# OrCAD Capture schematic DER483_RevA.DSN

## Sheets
1 PAGE2: size C
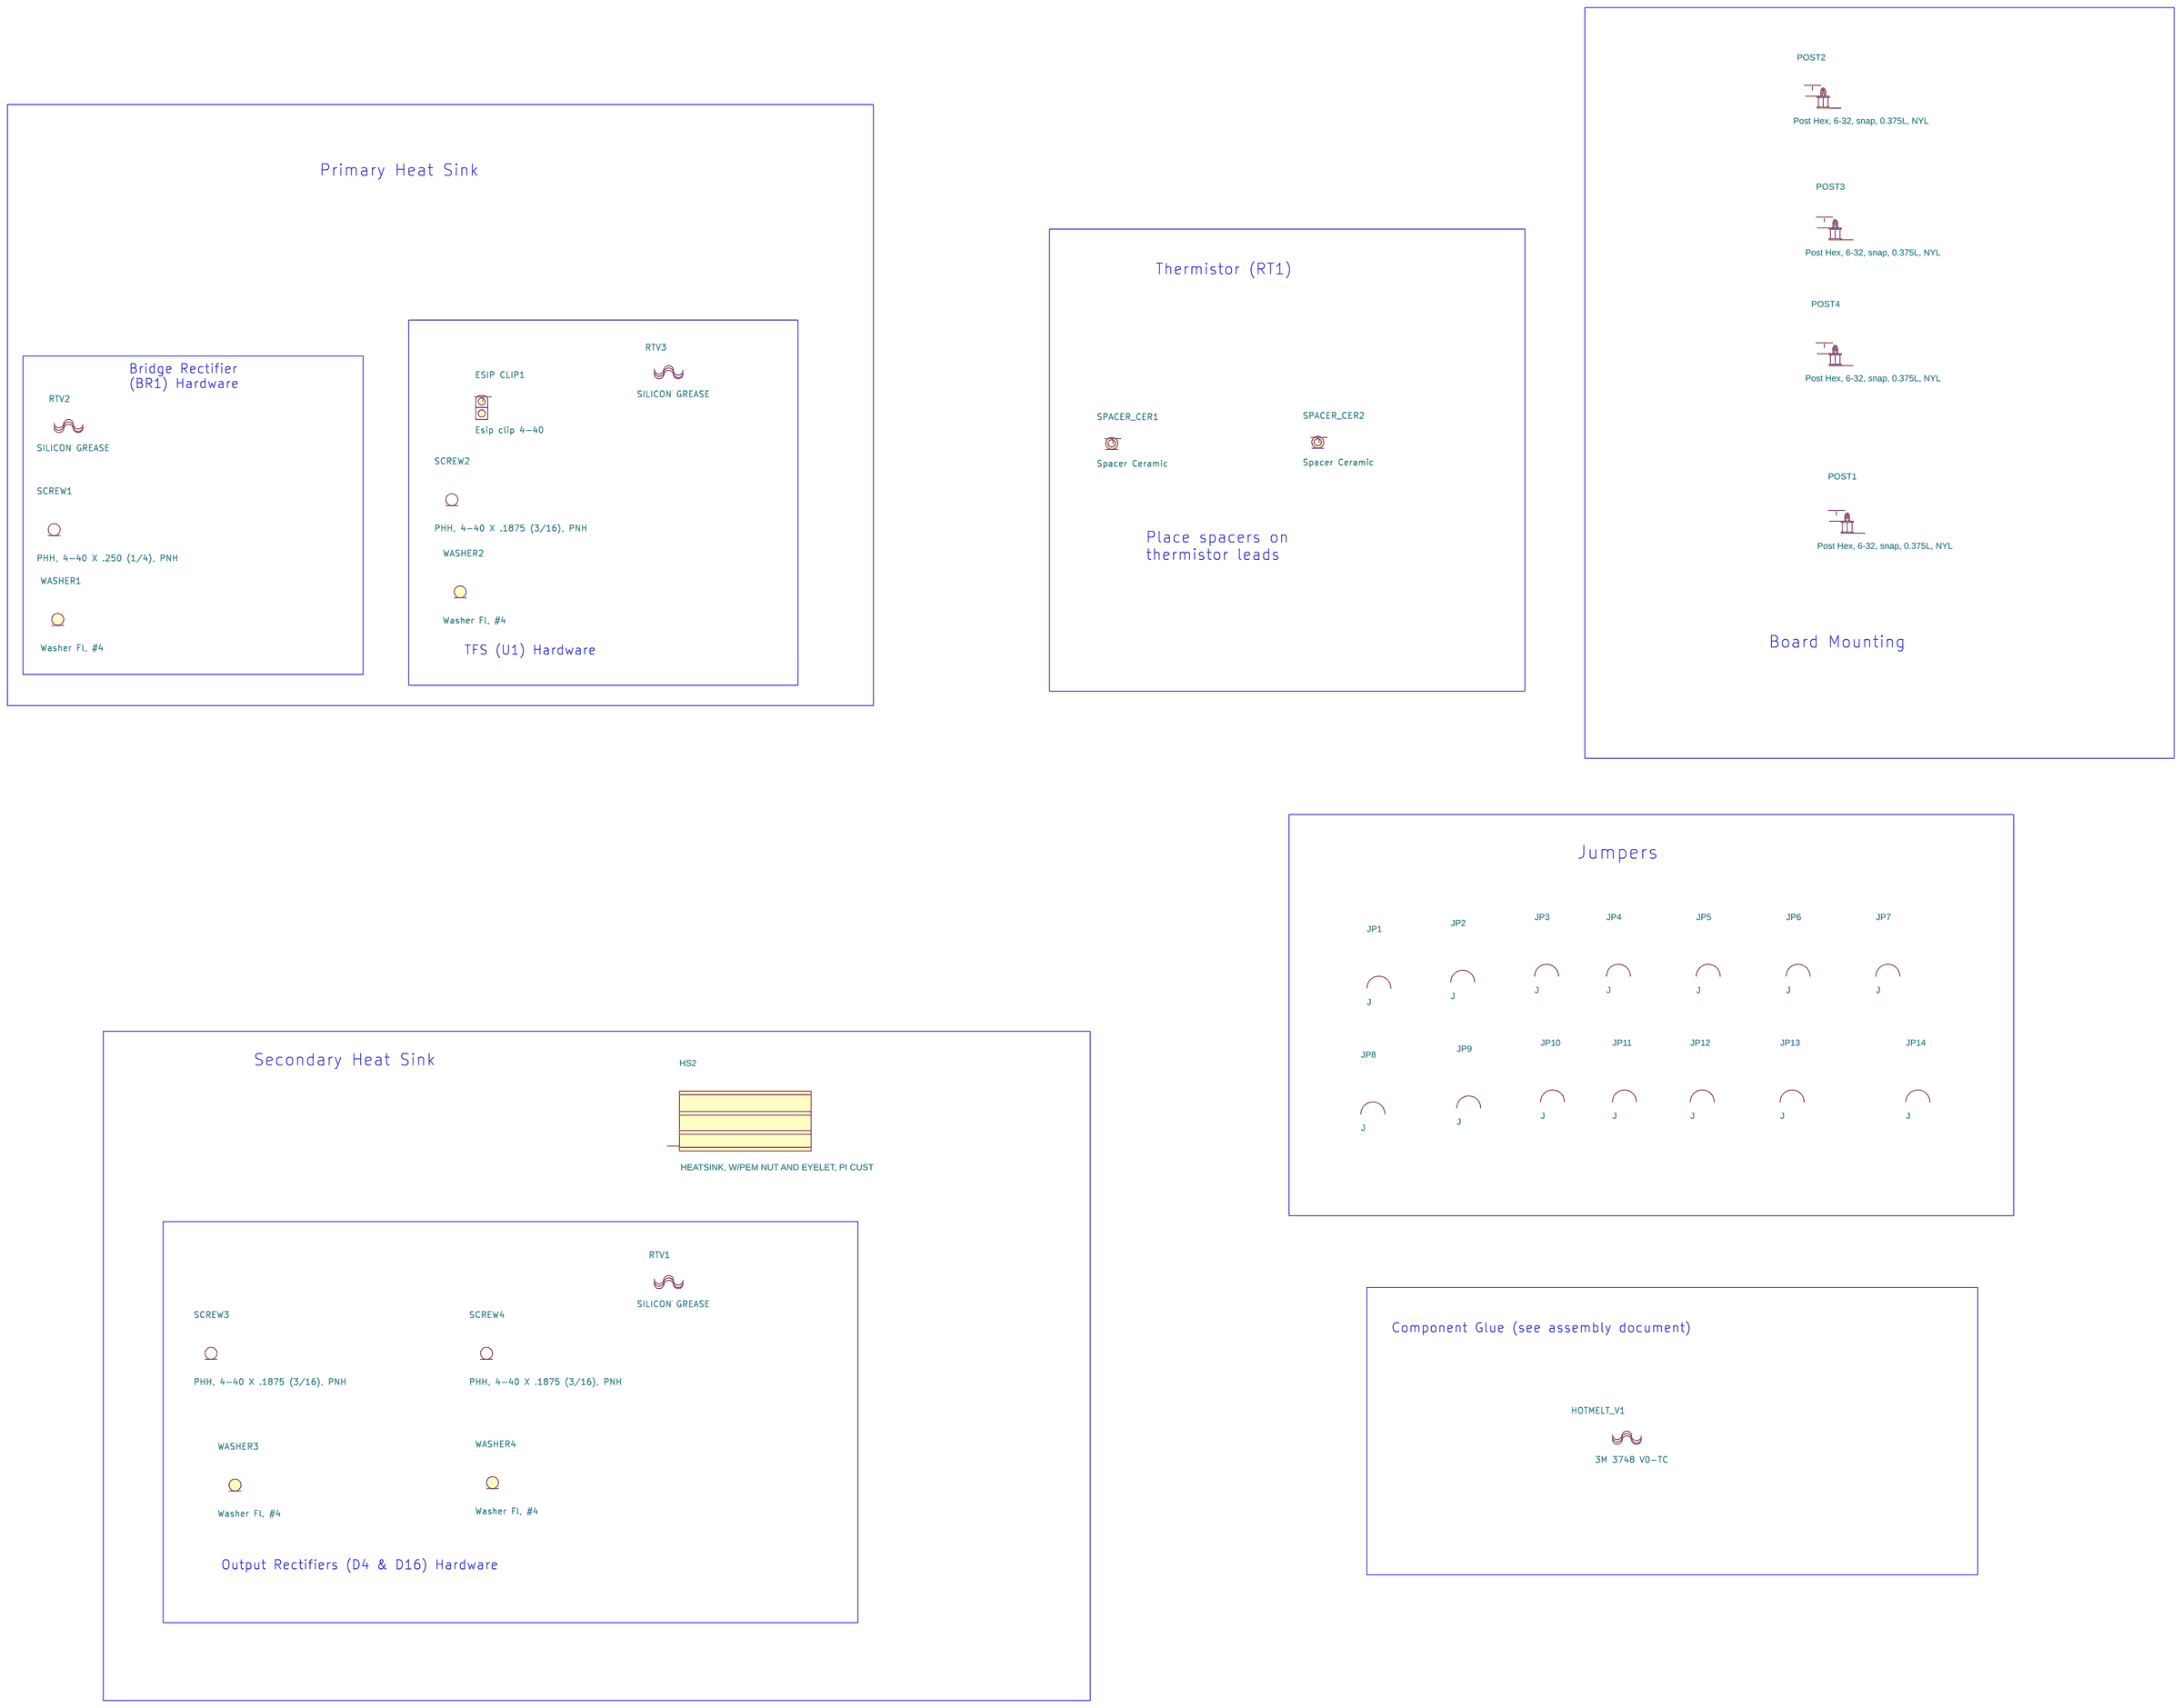
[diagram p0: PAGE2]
2 PAGE1: size C; title: DER-309; rev: A
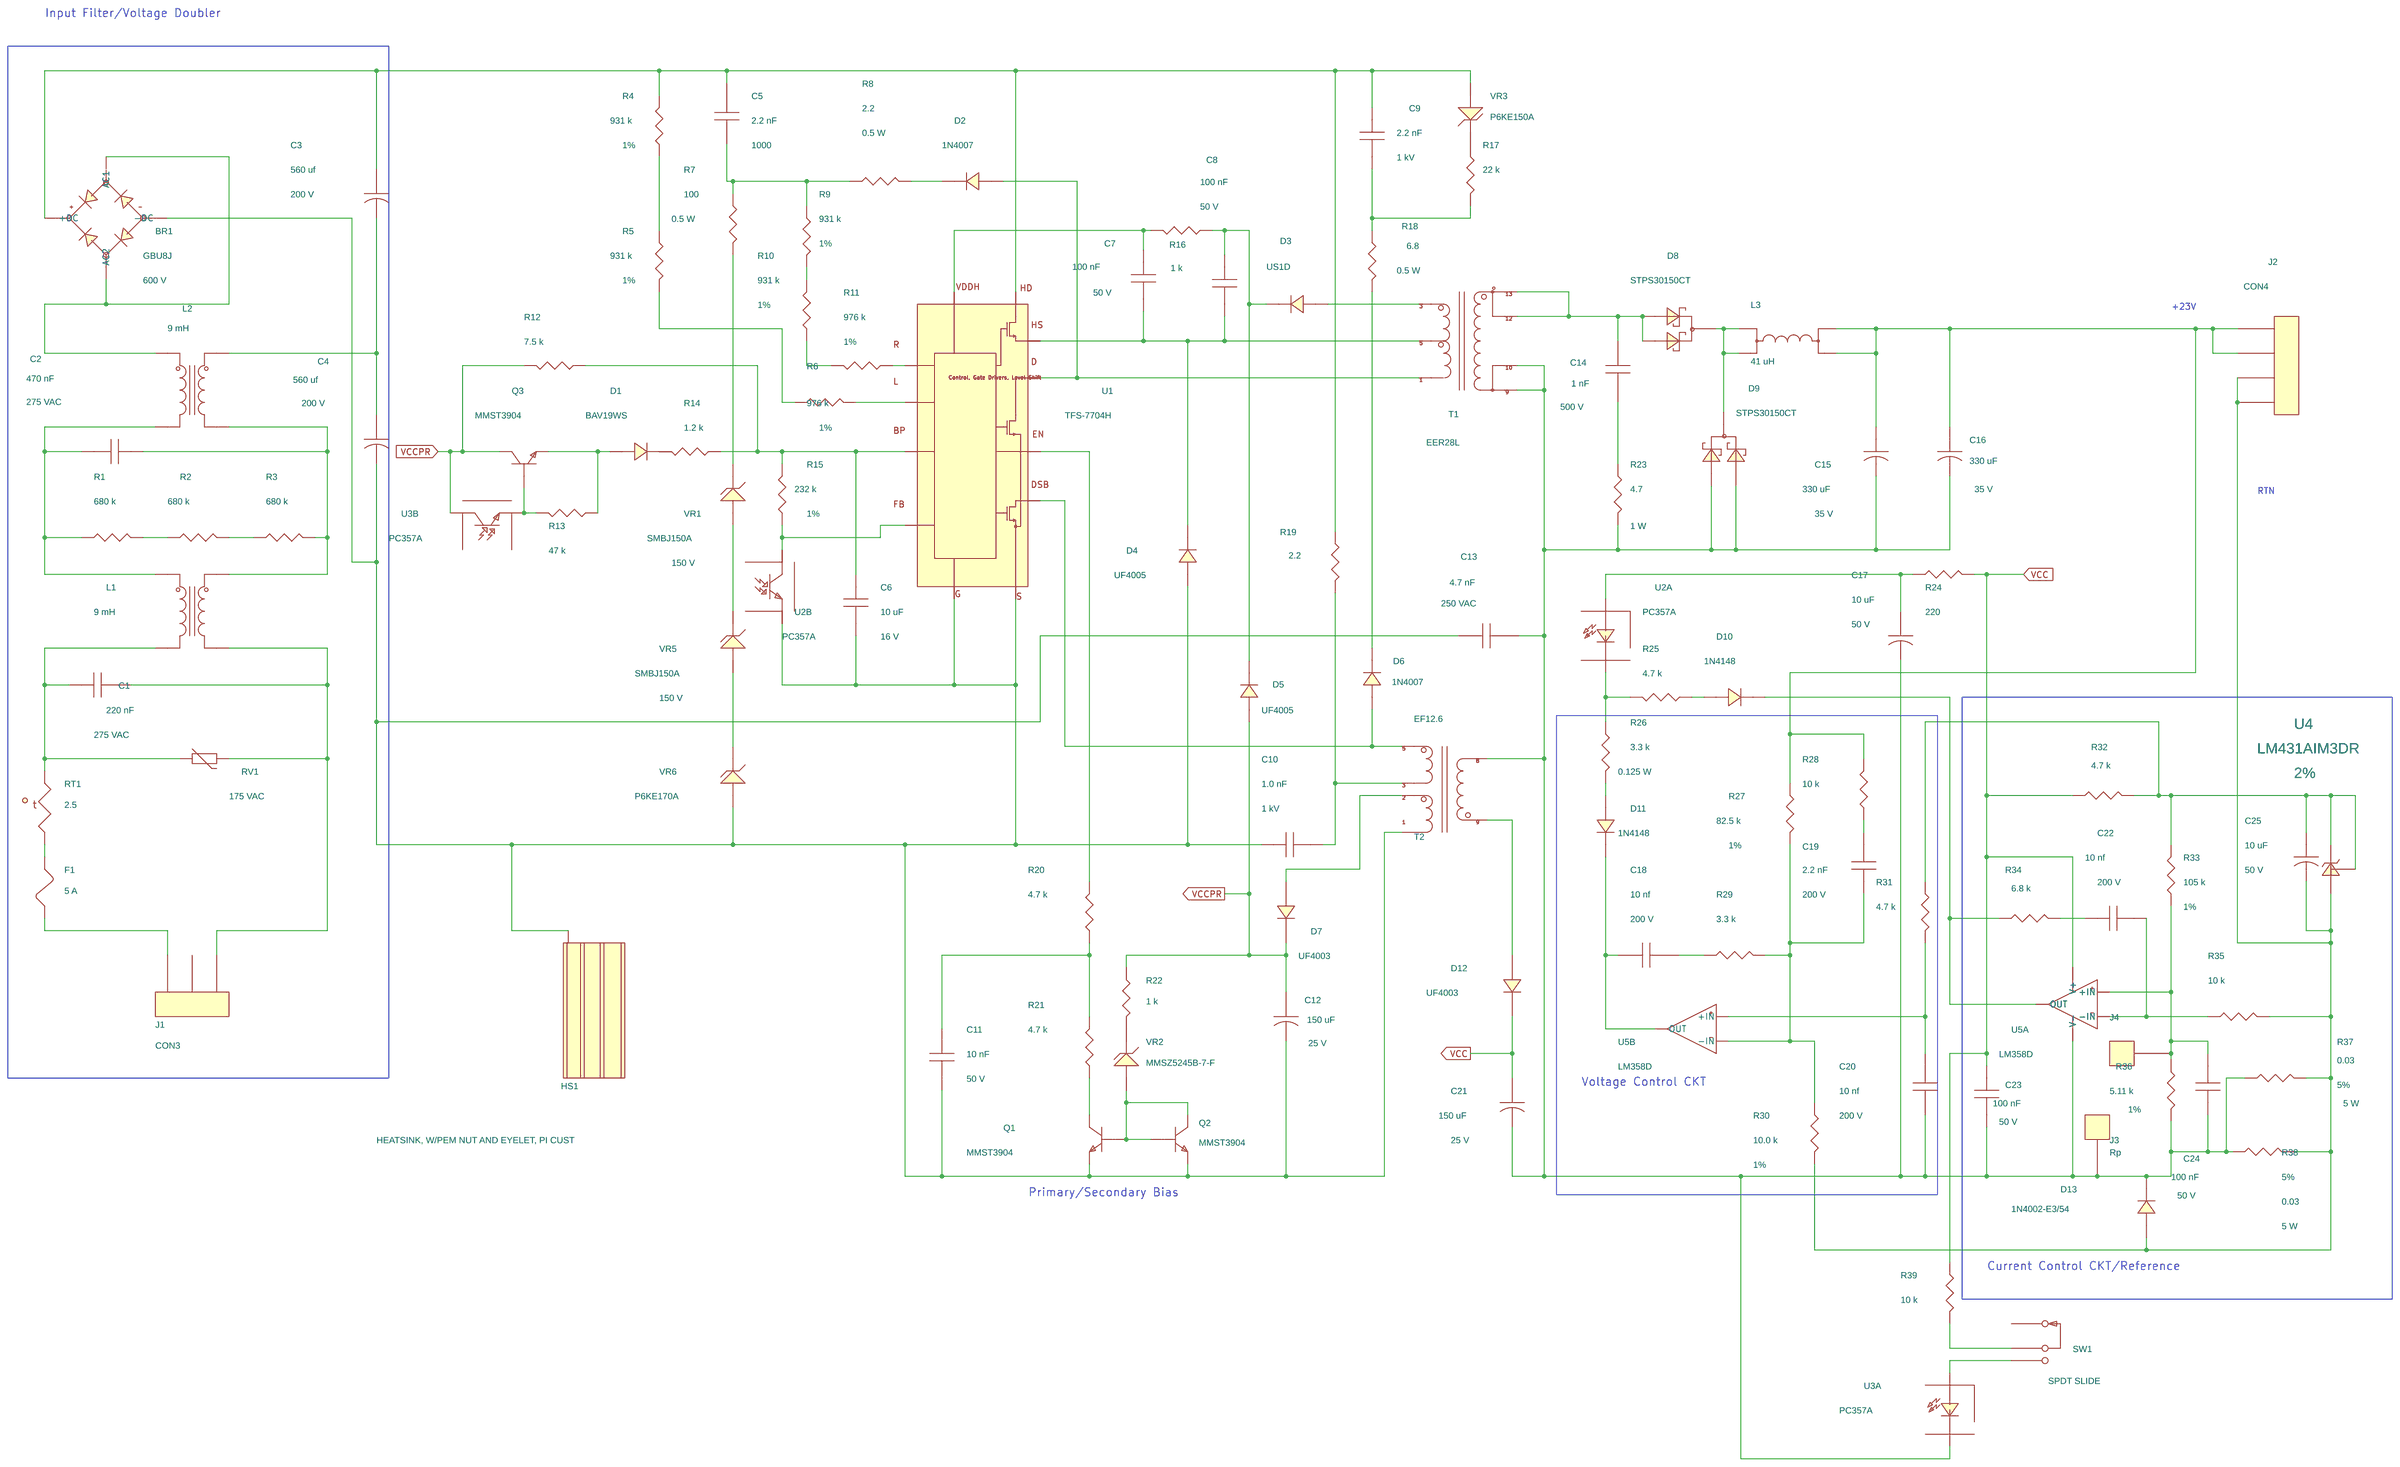
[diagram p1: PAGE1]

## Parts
sheet PAGE1
BR1  GBU8J  [pidaxbridgegbu8]
C1  220 nF  [pinpxcaprad720x340590040]
C2  470 nF  [pi_np_cap700x355ls600d040]
C3  560 uf  [pipolcapclyd710ls300040]
C4  560 uf  [pipolcapclyd710ls300040]
C5  2.2 nF  [pinpcaprad200x100200030]
C6  10 uF  [pinpcaprad200x100200030]
C7  100 nF  [pismc0603]
C8  100 nF  [pismc0603]
C9  2.2 nF  [pinpcaprad350x100200030]
C10  1.0 nF  [pinpcaprad290x160250030]
C11  10 nF  [pismc0603]
C12  150 uF  [pipolcapcyld250ls100030]
C13  4.7 nF  [pinpcaprad640x260375040]
C14  1 nF  [pinpcaprad250x100200030]
C15  330 uF  [pipolcapcyld400ls200040]
C16  330 uF  [pipolcapcyld400ls200040]
C17  10 uF  [pipolcapclyd200ls80030]
C18  10 nf  [pismc0805]
C19  2.2 nF  [pismc0805]
C20  10 nf  [pismc0805]
C21  150 uF  [pipolcapcyld250ls100030]
C22  10 nf  [pismc0805]
C23  100 nF  [pismc0805]
C24  100 nF  [pismc0805]
C25  10 uF  [pipolcapclyd200ls80030]
D1  BAV19WS  [pismsod323]
D2  1N4007  [pidax475x125040do41]
D3  US1D  [pismdsma]
D4  UF4005  [pidax475x125040do41]
D5  UF4005  [pidax475x125040do41]
D6  1N4007  [pidv200x110x040do41]
D7  UF4003  [pidv200x110x040do41]
D8  STPS30150CT  [pidvto2203vf1]
D9  STPS30150CT  [pidvto2203vf1]
D10  1N4148  [pidax375x070030do35]
D11  1N4148  [pidax375x070030do35]
D12  UF4003  [pidv200x110x040do41]
D13  1N4002-E3/54  [pidv200x110x040do41]
F1  5 A  [pi_tr5_submin_fuse]
HS1  HEATSINK, W/PEM NUT AND EYELET, PI CUST  [pi_hs_der483_bridge_esip]
J1  CON3  [pi_hdr_3pin]
J2  CON4  [PI_HDR_4PIN]
J3  Rp  [pi_hole_30awg]
J4  PCB Terminal 30 AWG  [pi_hole_30awg]
L1  9 mH  [pi_ind_4p_500x1050ls450d46]
L2  9 mH  [pi_ind_4p_500x1050ls450d46]
L3  41 uH  [pi_ind_4p_toroidal]
Q1  MMST3904  [pismsot323132]
Q2  MMST3904  [pismsot323132]
Q3  MMST3904  [pismsot323132]
R1  680 k  [pismr1206]
R2  680 k  [pismr1206]
R3  680 k  [pismr1206]
R4  931 k  [pismr1206]
R5  931 k  [pismr1206]
R6  976 k  [pismr1206]
R7  100  [pi12wresd180ls675d040]
R8  2.2  [pi12wvresd180ls150d040]
R9  931 k  [pismr1206]
R10  931 k  [pismr1206]
R11  976 k  [pismr1206]
R12  7.5 k  [pismr0805]
R13  47 k  [pismr0603]
R14  1.2 k  [pismr0805]
R15  232 k  [pismr0805]
R16  1 k  [pismr0603]
R17  22 k  [pi14wvresd100ls100d030]
R18  6.8  [pi12wvresd180ls150d040]
R19  2.2  [pi12wvresd180ls150d040]
R20  4.7 k  [pismr0603]
R21  4.7 k  [pismr0603]
R22  1 k  [pismr0603]
R23  4.7  [pi1wvresd200ls200d040]
R24  220  [pismr1206]
R25  4.7 k  [pismr1206]
R26  3.3 k  [pi18wresd080ls300d030]
R27  82.5 k  [pi14wresd100ls500d030]
R28  10 k  [pi14wvresd100ls100d030]
R29  3.3 k  [pismr0805]
R30  10.0 k  [pi14wresd100ls400d030]
R31  4.7 k  [pi14wresd100ls500d030]
R32  4.7 k  [pismr1206]
R33  105 k  [pismr1206]
R34  6.8 k  [pismr1206]
R35  10 k  [pismr0805]
R36  5.11 k  [pi14wresd100ls400d030]
R37  0.03  [pi_5w_res_550x200ls394d040]
R38  0.03  [pi_5w_res_550x200ls394d040]
R39  10 k  [pismr0805]
RT1  2.5  [pi_rad180x395ls235d031]
RV1  175 VAC  [pi_disc_575x320_ls335x140d040]
SW1  SPDT SLIDE  [pi_switch_spdt_slide_pcbm_1]
T1  EER28L  [pi_bobbin_eer28l_14p_der483]
T2  EF12.6  [pi_bobbin_ef126_9p_der483]
U1  TFS-7704H  [pi_ic_esip16-12_oval_slot]
U2  PC357A  [pi_4_smd]  (sections A,B)
U3  PC357A  [pi_4_smd]  (sections A,B)
U4  LM431AIM3DR  [pismsot23123]
U5  LM358D  [pismso8]  (sections A,B)
VR1  SMBJ150A  [pismdo214aa12]
VR2  MMSZ5245B-7-F  [pi_sm_sod-123_12]
VR3  P6KE150A  [pidv200x140x050do15do204ac]
VR5  SMBJ150A  [pismdo214aa12]
VR6  P6KE170A  [pidax550x140050do15do204ac]
sheet PAGE2
ESIP CLIP1  Esip clip 4-40
HOTMELT_V1  3M 3748 V0-TC
HS2  HEATSINK, W/PEM NUT AND EYELET, PI CUST  [pi_hs_der483_diodes]
JP1  J  [pi_jumper500-18awg-sld]
JP2  J  [pi_jumper600-18awg-sld]
JP3  J  [pi_jumper500]
JP4  J  [pi_jumper700-18awg-sld]
JP5  J  [pi_jumper600]
JP6  J  [pi_jumper600]
JP7  J  [pi_jumper700-18awg-sld]
JP8  J  [pi_jumper800]
JP9  J  [pi_jumper500]
JP10  J  [pi_jumper200]
JP11  J  [pi_jumper500]
JP12  J  [pi_jumper300]
JP13  J  [pi_jumper500]
JP14  J  [pi_jumper500-18awg-sld]
POST1  Post Hex, 6-32, snap, 0.375L, NYL  [pimtgholed156]
POST2  Post Hex, 6-32, snap, 0.375L, NYL  [pimtgholed156]
POST3  Post Hex, 6-32, snap, 0.375L, NYL  [pimtgholed156]
POST4  Post Hex, 6-32, snap, 0.375L, NYL  [pimtgholed156]
RTV1  SILICON GREASE
RTV2  SILICON GREASE
RTV3  SILICON GREASE
SCREW1  PHH, 4-40 X .250 (1/4), PNH
SCREW2  PHH, 4-40 X .1875 (3/16), PNH
SCREW3  PHH, 4-40 X .1875 (3/16), PNH
SCREW4  PHH, 4-40 X .1875 (3/16), PNH
SPACER_CER1  Spacer Ceramic
SPACER_CER2  Spacer Ceramic
WASHER1  Washer Fl, #4
WASHER2  Washer Fl, #4
WASHER3  Washer Fl, #4
WASHER4  Washer Fl, #4

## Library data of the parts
BR1 = DISCRETE_BRIDGE_+~~-: Disp_Voltage: 600 V; Part Number: 15-00720-00
C1 = CAP_NP: Disp_Voltage: 275 VAC; Part Number: 20-00386-00; Voltage: 275 VAC
C2 = CAP_NP: COMPGROUP: 1; Disp_Voltage: 275 VAC; PCB Editor PCBFP: pinpxcaprad720x340590040; Part Number: 20-01169-00; Tol: 20; Voltage: 275 VAC
C3 C4 = CAP_POL: Disp_Voltage: 200 V; Part Number: 24-00028-00; Voltage: 200 V
C5 = CAP_NP: Disp_Voltage: 1000; Part Number: 20-01093-00; Voltage: 1000
C6 = CAP_NP: Disp_Voltage: 16 V; Part Number: 20-01172-00; Voltage: 16 V
C7 C8 = CAP_NP: Disp_Voltage: 50 V; Part Number: 20-00936-00; Voltage: 50 V
C9 = CAP_NP: Disp_Voltage: 1 kV; Part Number: 20-00357-00; Voltage: 1 kV
C10 = CAP_NP: Disp_Voltage: 1 kV; Part Number: 20-00662-00; Voltage: 1 kV
C11 = CAP_NP: Disp_Voltage: 50 V; Part Number: 20-01051-00; Voltage: 50V
C12 C21 = CAP_POL: COMPGROUP: 1; Disp_Voltage: 25 V; Part Number: 20-00096-00; Tol: 20; Voltage: 25 V
C13 = CAP_NP: Disp_Voltage: 250 VAC; Part Number: 20-00378-00; Voltage: 250 VAC
C14 = CAP_NP: Disp_Voltage: 500 V; Part Number: 20-00621-00; Voltage: 500 V
C15 C16 = CAP_POL: ALT_SYMBOLS: pipolcapclyd395x630ls200030h; Disp_Voltage: 35 V; FPLIST: pipolcapcyld400ls200040,pipolcapclyd395x630ls200030h; Part Number: 20-00122-00; Voltage: 35 V
C17 C25 = CAP_POL: ALT_SYMBOLS: pipolcapclyd200ls80030h; Disp_Voltage: 50 V; FPLIST: pipolcapclyd200ls80030,pipolcapclyd200ls80030h; Part Number: 20-00443-00; Voltage: 50 V
C18 C20 C22 = CAP_NP: Disp_Voltage: 200 V; Part Number: 20-00531-00; Voltage: 200 V
C19 = CAP_NP: Disp_Voltage: 200 V; Part Number: 20-00761-00; Voltage: 200 V
C23 C24 = CAP_NP: Disp_Voltage: 50 V; Part Number: 20-00904-00; Voltage: 50 V
D1 = DIODE: Part Number: 15-00658-00
D2 D6 = DIODE: ALT_SYMBOLS: pidax475x125040do41,pidv200x110x040do41wbead,pidax390x125040do41; FPLIST: pidv200x110x040do41,pidax475x125040do41,pidv200x110x040do41wbead,pidax390x125040do41; Part Number: 15-00623-00
D3 = DIODE: Part Number: 15-00492-00
D4 D5 = DIODE: ALT_SYMBOLS: pidax475x125040do41,pidax390x125040do41; FPLIST: pidv200x110x040do41,pidax475x125040do41,pidax390x125040do41; Part Number: 15-00109-00
D7 D12 = DIODE: ALT_SYMBOLS: pidax475x125040do41,pidv200x110x040do41wbead,pidax390x125040do41; COMPGROUP: 1; FPLIST: PI_DV/.200X.110X.040/DO_41,PI_DAX/.475X.125/.040/DO_41,PI_DV/.200X.110X.040/DO_41_WBEAD,PI_DAX/.390X.125/.040/DO_41; Part Number: 15-00107-00
D8 D9 = DS_DUAL_CK_A_AC: FPLIST: pidvto2203,pidvto2203vf1,pidvto2203vf1h; Part Number: 15-00914-00
D10 D11 = DIODE: ALT_SYMBOLS: pidax375x070030do35,pidv100x080x030do35; FPLIST: pidv200x080x030do35,pidax375x070030do35,pidv100x080x030do35; Part Number: 15-00083-00
D13 = DIODE: ALT_SYMBOLS: pidax475x125040do41,pidv200x110x040do41wbead,pidax390x125040do41; FPLIST: pidv200x110x040do41,pidax475x125040do41,pidv200x110x040do41wbead,pidax390x125040do41; Part Number: 15-00792-00
F1 = FUSE: COMPGROUP: 1; Part Number: 40-00005-00; Voltage: 250 V
HS1 = HS-PI_CUSTOM1: Part Number: 61-00199-01
J1 = CON3: COMPGROUP: 1; Part Number: 35-00002-00
J2 = CON4: COMPGROUP: 2; Part Number: 35-00003-00
J3 J4 = TERM_1Pin: Part Number: 35-00026-00
L1 L2 = INDUCTOR_4P_REVB_0: Part Number: 30-00235-00
L3 = INDUCTOR_4P_SD: Part Number: 32-00326-00
Q1-Q3 = NPN_BEC: Part Number: 55-00016-00
R1-R3 = R: Part Number: 05-01420-00
R4 R9 R10 = R: Disp_Tol: 1%; Part Number: 05-00478-00
R5 = R: COMPGROUP: 2; Disp_Tol: 1%; Part Number: 05-00478-00; Tol: 1%
R6 = R: COMPGROUP: 2; Disp_Tol: 1%; Part Number: 05-00480-00; Tol: 1%
R7 = R: ALT_SYMBOLS: pi12wvresd180ls200d040,pi12wvresd180ls250d040,pi12wresd180ls675d040; Disp_Power: 0.5 W; FPLIST: pi12wvresd180ls150d040,pi12wvresd180ls200d040,pi12wvresd180ls250d040,pi12wresd180ls675d040; Part Number: 05-05569-00
R8 = R: ALT_SYMBOLS: pi12wvresd180ls200d040,pi12wvresd180ls250d040,pi12wresd180ls675d040; Disp_Power: 0.5 W; FPLIST: pi12wvresd180ls150d040,pi12wvresd180ls200d040,pi12wvresd180ls250d040,pi12wresd180ls675d040; Part Number: 05-02611-00
R11 = R: Disp_Tol: 1%; Part Number: 05-00480-00
R12 = R: Part Number: 05-01540-00
R13 = R: Part Number: 05-01728-00
R14 = R: Part Number: 05-01521-00
R15 = R: Disp_Tol: 1%; Part Number: 05-00815-00
R16 = R: COMPGROUP: 2; PCB Editor PCBFP: pismr0805; Part Number: 05-01688-00; Tol: 5%
R17 = R: ALT_SYMBOLS: pi14wvresd100ls200d030,pi14wresd100ls400d030,pi14wresd100ls500d030; FPLIST: pi14wvresd100ls100d030,pi14wvresd100ls200d030,pi14wresd100ls400d030,pi14wresd100ls500d030; Part Number: 05-02539-00
R18 = R: ALT_SYMBOLS: pi12wvresd180ls200d040,pi12wvresd180ls250d040,pi12wresd180ls675d040; Disp_Power: 0.5 W; FPLIST: pi12wvresd180ls150d040,pi12wvresd180ls200d040,pi12wvresd180ls250d040,pi12wresd180ls675d040; Part Number: 05-02623-00
R19 = R: ALT_SYMBOLS: pi12wvresd180ls200d040,pi12wvresd180ls250d040,pi12wresd180ls675d040; FPLIST: pi12wvresd180ls150d040,pi12wvresd180ls200d040,pi12wvresd180ls250d040,pi12wresd180ls675d040; Part Number: 05-05578-00
R20 R21 = R: Part Number: 05-01704-00
R22 = R: Part Number: 05-01688-00
R23 = R: ALT_SYMBOLS: pi1wvresd120ls200d040,pi1wvresd120ls300d040,pi1wvresd200ls200d040,pi1wvresd200ls300d040,pi1wvresd200ls350d040; Disp_Power: 1 W; FPLIST: pi1wresd200ls725d040,pi1wvresd120ls200d040,pi1wvresd120ls300d040,pi1wvresd200ls200d040,pi1wvresd200ls300d040,pi1wvresd200ls350d040; Part Number: 05-02796-00
R24 = R: Part Number: 05-01336-00
R25 R32 = R: Part Number: 05-01368-00
R26 = R: Disp_Power: 0.125 W; FPLIST: pi18wvresd80ls100d030,pi18wresd080ls300d030; Part Number: 05-02349-00
R27 = R: ALT_SYMBOLS: pi14wvresd100ls200d030,pi14wresd100ls400d030,pi14wresd100ls500d030; Disp_Tol: 1%; FPLIST: pi14wvresd100ls100d030,pi14wvresd100ls200d030,pi14wresd100ls400d030,pi14wresd100ls500d030; Part Number: 05-02160-00
R28 = R: ALT_SYMBOLS: pi14wvresd100ls200d030,pi14wresd100ls400d030,pi14wresd100ls500d030; FPLIST: pi14wvresd100ls100d030,pi14wvresd100ls200d030,pi14wresd100ls400d030,pi14wresd100ls500d030; Part Number: 05-02531-00
R29 = R: Part Number: 05-01531-00
R30 = R: ALT_SYMBOLS: pi14wvresd100ls200d030,pi14wresd100ls400d030,pi14wresd100ls500d030; Disp_Tol: 1%; FPLIST: pi14wvresd100ls100d030,pi14wvresd100ls200d030,pi14wresd100ls400d030,pi14wresd100ls500d030; Part Number: 05-05421-00
R31 = R: ALT_SYMBOLS: pi14wvresd100ls200d030,pi14wresd100ls400d030,pi14wresd100ls500d030; FPLIST: pi14wvresd100ls100d030,pi14wvresd100ls200d030,pi14wresd100ls400d030,pi14wresd100ls500d030; Part Number: 05-02523-00
R33 = R: Disp_Tol: 1%; Part Number: 05-00387-00
R34 = R: Part Number: 05-01372-00
R35 = R: COMPGROUP: 5; Part Number: 05-01543-00; Tol: 1%
R36 = R: ALT_SYMBOLS: pi14wvresd100ls200d030,pi14wresd100ls400d030,pi14wresd100ls500d030; Disp_Tol: 1%; FPLIST: pi14wvresd100ls100d030,pi14wvresd100ls200d030,pi14wresd100ls400d030,pi14wresd100ls500d030; Part Number: 05-02044-00
R37 R38 = R: Disp_Power: 5 W; Disp_Tol: 5%; Part Number: 05-05581-00
R39 = R: Part Number: 05-01543-00
RT1 = THERMISTOR: FPLIST: pi_rad180x395ls235d031,pirad550x410ls300040_h; Part Number: 90-00038-00
RV1 = VARISTOR: COMPGROUP: 1; Part Number: 85-00029-00
SW1 = SW_SLIDE-SPDT: Part Number: 66-00111-00
T1 = BEER28L_CUSTOM_DER483: Part Number: 25-01071-00
T2 = BEF12.6_CUSTOM_DER483: Part Number: 25-01072-00
U1 = HiperTFS_II_I_2_ROW_2: ALT_SYMBOLS: pi_ic_esip16-12_oval_slot_recpt; FPLIST: pi_ic_esip16-12_oval_slot,pi_ic_esip16-12_oval_slot_recpt; Part Number: 10-00609-00
U2 U3 = OPTO_A_B: Part Number: 53-00003-00
U4 = TL431_SOT-23_CAR: Disp_Tol: 2%; Part Number: 45-00144-00; Tol: 2%
U5 = LM358: Part Number: 45-00050-00
VR1 VR5 = DIODE_ZENER: Disp_Voltage: 150 V; Part Number: 15-00427-00
VR2 = DIODE_ZENER: Part Number: 15-01091-00
VR3 = DIODE_ZENER: ALT_SYMBOLS: pidax550x140050do15do204ac; FPLIST: pidv200x140x050do15do204ac,pidax550x140050do15do204ac; Part Number: 15-00619-00
VR6 = DIODE_ZENER: FPLIST: pidv200x140x050do15do204ac,pidax550x140050do15do204ac; Part Number: 15-00617-00
ESIP CLIP1 = EsipClip_4-40: Part Number: 60-00037-00
HOTMELT_V1 = HOTMELT-V0: Part Number: 66-00077-00
HS2 = HS-PI_CUSTOM1: Part Number: 61-00200-01
JP1 JP14 = JUMPER_1: Part Number: 65-00083-00
JP2 = JUMPER_1: Part Number: 65-00084-00
JP3 JP9 JP11 JP13 = JUMPER_1: Part Number: 65-00122-00
JP4 JP7 = JUMPER_1: Part Number: 65-00085-00
JP5 JP6 = JUMPER_1: Part Number: 65-00123-00
JP8 = JUMPER_1: Part Number: 65-00125-00
JP10 = JUMPER_1: Part Number: 65-00119-00
JP12 = JUMPER_1: Part Number: 65-00120-00
POST1-POST4 = POST_CRKT_BRD_6-32_HEX: Part Number: 76-00003-00
RTV1-RTV3 = RTV: Part Number: 66-00084-00
SCREW1 = SCR_4-40: Part Number: 75-00001-00
SCREW2-SCREW4 = SCR_4-40: Part Number: 75-00089-00
SPACER_CER1 SPACER_CER2 = Spacer_Ceramic: Part Number: 76-00031-00
WASHER1 = WASH_FLAT_4: Part Number: 75-00032-00
WASHER2-WASHER4 = WASH_FLAT_4: Part Number: 75-00164-00

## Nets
VCC: C21.1 C23.1 D12.1 R24.2 R32.1 R39.1 U5.8(V+)
VCCPR: C12.1 D5.2 D7.1 Q3.3(COLLECTOR) R12.1 R22.1 U3.4(C)
N5956925: BR1.4(-DC) C4.2 C6.2 C10.1 C11.2 C12.2 C13.1 D4.2 HS1.1 Q1.2(EMITTER) Q2.2(EMITTER) T2.1 U1.5(G) U1.6(S) U2.3(E) VR6.2
N6240208: R5.2 R6.1
N6451090: C13.2 C15.2 C16.2 C17.2 C20.1 C21.2 C23.2 C24.1 D9.1(A1) D9.3(A2) D13.1 J3.1 R23.2 R36.2 R37.1 R38.1 T1.9 T1.10 T2.8 U3.2(C) U5.4(V-)
N6900286: BR1.1(+DC) C3.1 C5.2 C9.1 R4.2 R19.1 U1.16(HD) VR3.2
N7093005: C25.2 D13.2 J2.3 J2.4 R30.2 R35.2 R37.2 R38.2 U4.2(A)
N8059193: C1.1 L1.3 RT1.2 RV1.1
N8059197: F1.1 J1.1
N8059233: C2.1 L1.4 L2.2 R3.2
N8059379: R1.2 R2.1
N8059399: R2.2 R3.1
N8059437: C1.2 J1.3 L1.2 RV1.2
N8059489: C2.2 L1.1 L2.3 R1.1
N8060888: BR1.2(AC1) BR1.3(AC2) L2.1
N8067300: C15.1 C16.1 J2.1 J2.2 L3.3 L3.4 R27.1 R28.2
N8070264: D10.2 R25.1
N8070276: C25.1 R31.1 R32.2 R33.2 U4.1(C) U4.3(VREF)
N8070304: C18.1 D11.1 U5.7(OUT)
N8070334: C19.1 R27.2 R29.2 R30.1 U5.6(-IN)
N8070466: C20.2 R31.2 U5.5(+IN)
N8070478: R25.2 R26.1 U2.2(C)
N8070490: D10.1 R34.1 U5.1(OUT)
N8070648: C22.2 R35.1 U5.2(-IN)
N8071028: C24.2 J4.1 R33.1 R36.1 U5.3(+IN)
N8073566: C3.2 C4.1 L2.4
N8079055: C17.1 R24.1 U2.1(A)
N8088388: F1.2 RT1.1
N8130547: R39.2 SW1.2
N8135210: C22.1 R34.2
N8194184: C7.2 C8.2 D4.1 T1.5 U1.14(HS)
N8194788: D2.2 T1.1 U1.1(D)
N8195110: D6.2 T2.5 U1.3(DSB)
N8203179: C14.1 D8.1(A1) D8.3(A2) T1.12 T1.13
N8204013: D7.2 T2.2
N8204160: Q1.1(BASE) Q2.1(BASE) Q2.3(COLLECTOR) VR2.2
N8204208: R20.2 U1.8(EN)
N8204226: Q1.3(COLLECTOR) R21.1
N8207135: C8.1 D3.1 D5.1 R16.2
N8207503: C7.1 R16.1 U1.13(VDDH)
N8207747: C6.1 R12.2 R14.1 R15.1 U1.11(BP)
N8207786: R15.2 U1.10(FB) U2.4(C)
N8210623: C9.2 R17.2 R18.1
N8210650: C10.2 R19.2 T2.3
N8210678: D6.1 R18.2
N8213244: C11.1 R20.1 R21.2
N8214579: R10.2 R11.2
N8215069: R11.1 U1.7(R)
N8245190: R4.1 R5.1
N8273380: R6.2 U1.9(L)
N8278408: SW1.3 U3.1(A)
N8282330: VR1.2 VR5.1
N8282334: C5.1 R7.2 R8.1 R9.1
N8284139: Q3.1(BASE) R13.1 U3.3(E)
N8284357: R7.1 VR1.1
N8284401: VR5.2 VR6.1
N8289100: D8.2(K) D9.2(K) L3.1 L3.2
N8290901: C14.2 R23.1
N8295742: R9.2 R10.1
N8298855: D1.2 Q3.2(EMITTER) R13.2
N8307586: D2.1 R8.2
N8312003: D1.1 R14.2
N8332239: D11.2 R26.2
N8339978: C18.2 R29.1
N8340626: C19.2 R28.1
N8356117: D12.2 T2.9
N8358108: D3.2 T1.3
N8364547: R17.1 VR3.1
N8364666: R22.2 VR2.1

Not connected (* = marked no-connect by the designer): HS2 1; J1 2; JP1 1 2; JP2 1 2; JP3 1 2; JP4 1 2; JP5 1 2; JP6 1 2; JP7 1 2; JP8 1 2; JP9 1 2; JP10 1 2; JP11 1 2; JP12 1 2; JP13 1 2; JP14 1 2; POST1 1; POST2 1; POST3 1; POST4 1; SW1 1

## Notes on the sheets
sheet 1
- Primary Heat Sink
- Thermistor (RT1)
- Bridge Rectifier
  (BR1) Hardware
- Place spacers on
  thermistor leads
- TFS (U1) Hardware
- Board Mounting
- Jumpers
- Secondary Heat Sink
- Component Glue (see assembly document)
- Output Rectifiers (D4 & D16) Hardware
sheet 2
- Input Filter/Voltage Doubler
- +23V
- RTN
- Voltage Control CKT
- Primary/Secondary Bias
- Current Control CKT/Reference
